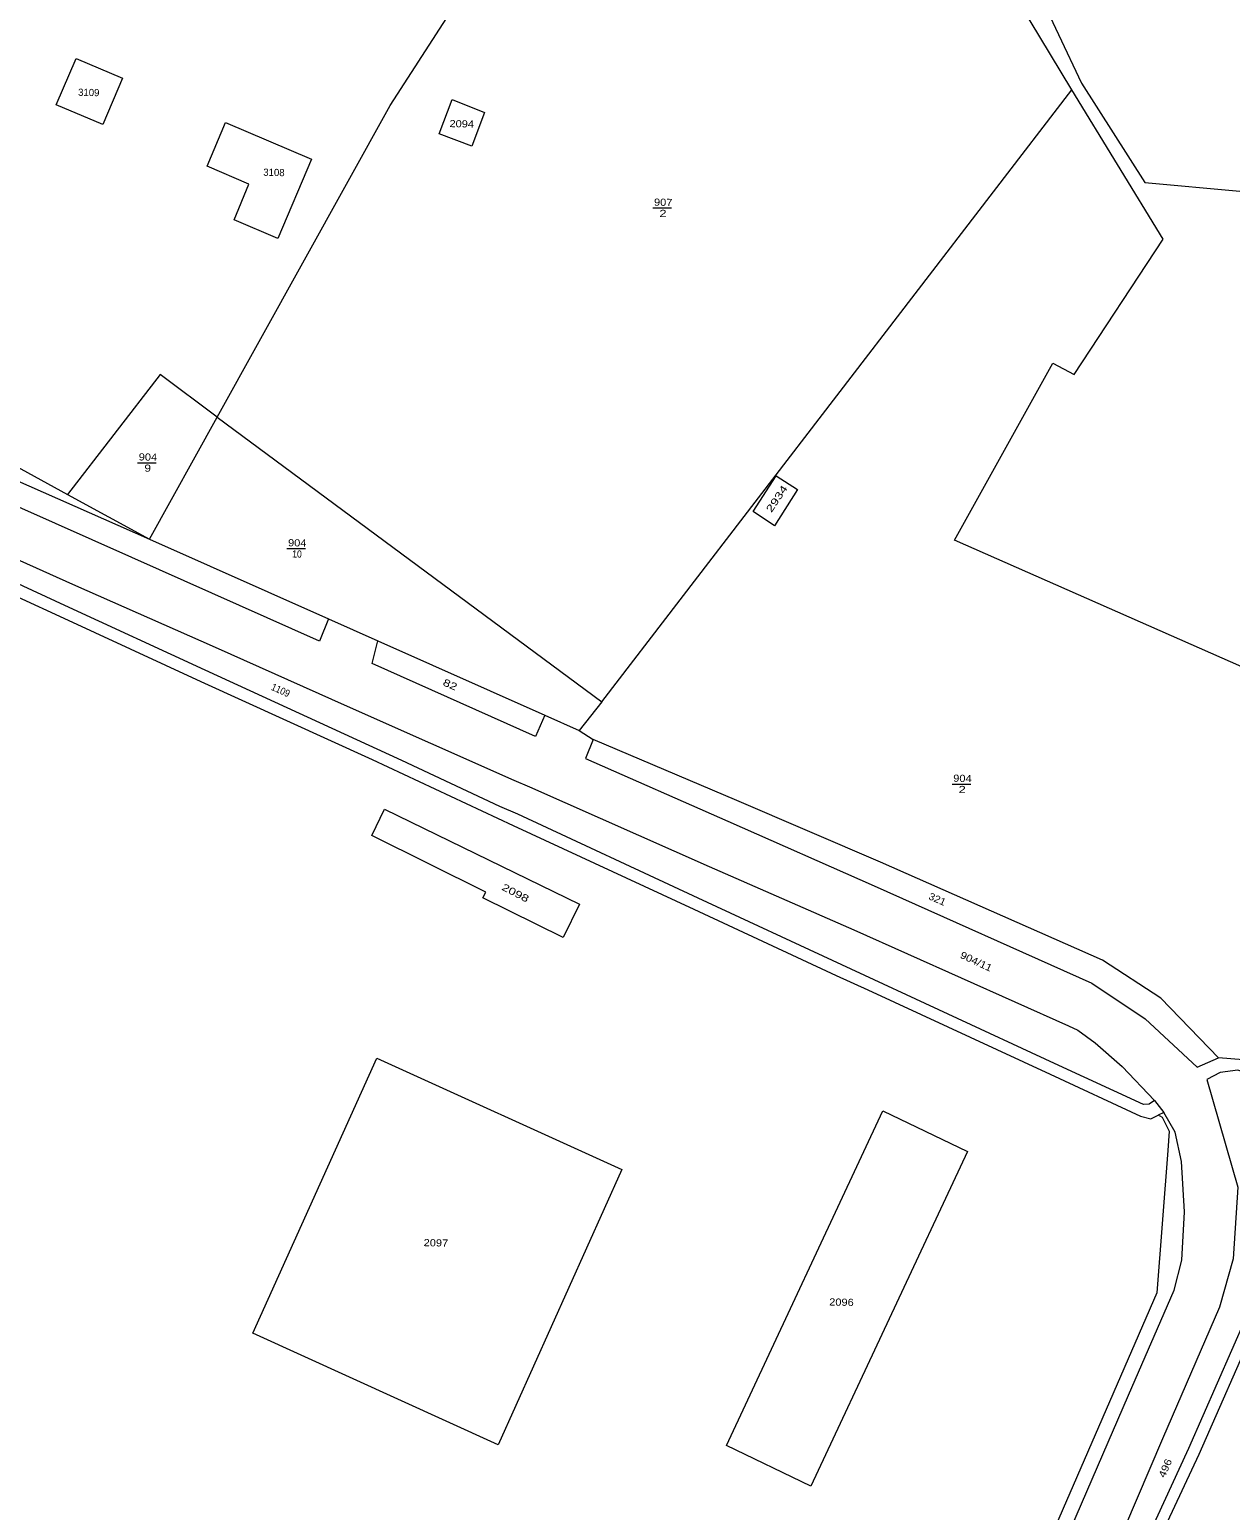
# Model space of a CAD drawing. Extents: x -843400 to -842830, y -1002860 to -1002082.
# Drawn here: x -843097.6 to -842930.2, y -1002726.5 to -1002520 of the extents above; entities that cross this region are included whole.
import ezdxf
from ezdxf.enums import TextEntityAlignment as Align

# ---------------------------------------------------------------- set-up
doc = ezdxf.new("R2010")
doc.units = 0
doc.header["$LTSCALE"] = 0.4
for name, color, linetype, lineweight in [('32', 7, 'Continuous', 13), ('34', 7, 'Continuous', 13), ('35', 7, 'Continuous', 13), ('38', 7, 'Continuous', 13), ('40', 7, 'Continuous', 13), ('43', 7, 'Continuous', 13)]:
    doc.layers.add(name, color=color, linetype=linetype, lineweight=lineweight)

msp = doc.modelspace()

# ---------------------------------------------------------------- linework, layer by layer
at = {"layer": '32'}
for p, q in [((-843017.83, -1002613.7), (-842952.33, -1002528.36)), ((-843055.92, -1002602.16), (-843049.06, -1002605.21)), ((-842940.79, -1002669.32), (-842939.49, -1002671))]:
    msp.add_line(p, q, dxfattribs=at)
for points in [[(-842917.26, -1002663.21), (-842904.25, -1002619.58), (-842968.69, -1002591.19), (-842954.99, -1002566.47), (-842952.01, -1002568.05), (-842939.57, -1002549.22), (-842952.33, -1002528.36), (-842968.38, -1002501.67), (-842999.65, -1002478.78), (-842992.16, -1002464.73), (-842985.04, -1002466.11)], [(-843071.44, -1002574), (-843047.33, -1002530.57), (-843031.55, -1002506.04), (-843010.14, -1002473.05)], [(-843211.56, -1002530.68), (-843208.79, -1002526.68), (-843203.39, -1002526.24), (-843127.17, -1002565.66), (-843092.3, -1002584.79), (-843080.9, -1002591.04)], [(-843215.33, -1002546.59), (-843193.12, -1002556.57), (-843172, -1002566.13), (-843153.26, -1002574.59), (-843132, -1002584.19), (-843109.23, -1002594.52), (-843093.46, -1002601.76), (-843073.75, -1002610.86), (-843049.84, -1002621.77), (-843030.19, -1002630.96), (-843005, -1002642.63), (-842985.15, -1002651.86), (-842980.77, -1002653.89), (-842955.35, -1002665.65), (-842942.73, -1002671.51), (-842941.29, -1002671.85), (-842940.287, -1002671.376)], [(-843080.9, -1002591.04), (-843071.44, -1002574), (-843079.42, -1002568.09), (-843092.3, -1002584.79)], [(-843071.44, -1002574), (-843017.83, -1002613.7), (-843021, -1002617.7)], [(-843025.79, -1002615.57), (-843021, -1002617.7), (-843019.03, -1002618.97)], [(-842949.73, -1002770.53), (-842948.12, -1002770.28), (-842947.09, -1002769.45), (-842946.99, -1002769.3), (-842946.43, -1002768.26), (-842946.36, -1002766.94), (-842947.25, -1002754.97), (-842947.02, -1002748.98), (-842946.95, -1002748.51), (-842945.3, -1002742.1), (-842942.37, -1002735.33), (-842934.56, -1002718.61), (-842926.46, -1002700.13), (-842920.81, -1002683.35), (-842919.88, -1002680.59), (-842915.57, -1002667.81), (-842928.42, -1002663.65), (-842931.89, -1002663.34)]]:
    msp.add_lwpolyline(points, dxfattribs=at)
at = {"layer": '34'}
for p, q in [((-843010.721, -1002544.851), (-843008.125, -1002544.851)), ((-843082.549, -1002580.375), (-843079.953, -1002580.375)), ((-843061.735, -1002592.345), (-843059.139, -1002592.345)), ((-842969.007, -1002625.185), (-842966.411, -1002625.185))]:
    msp.add_line(p, q, dxfattribs=at)
at = {"layer": '38'}
for points in [[(-843091.11, -1002524), (-843084.65, -1002526.76), (-843087.4, -1002533.21), (-843093.89, -1002530.47)], [(-843038.68, -1002529.71), (-843034.21, -1002531.52), (-843035.98, -1002536.21), (-843040.53, -1002534.5)], [(-843070.28, -1002532.94), (-843058.33, -1002538.06), (-843063.01, -1002549.11), (-843069.09, -1002546.48), (-843067.04, -1002541.51), (-843072.85, -1002539)], [(-842996.74, -1002587.18), (-842993.55, -1002582.19), (-842990.54, -1002584.1), (-842993.76, -1002589.17)], [(-843048.13, -1002628.68), (-843020.96, -1002641.94), (-843023.23, -1002646.57), (-843034.42, -1002641.06), (-843034, -1002640.24), (-843049.91, -1002632.37)], [(-843015.03, -1002678.95), (-843032.3, -1002717.35), (-843066.48, -1002701.76), (-843049.21, -1002663.43)], [(-843000.45, -1002717.4), (-842978.65, -1002670.77), (-842966.88, -1002676.43), (-842988.69, -1002723.07)]]:
    msp.add_lwpolyline(points, close=True, dxfattribs=at)
at = {"layer": '40'}
msp.add_lwpolyline([(-843160.48, -1002346.53), (-843130.91, -1002349.42), (-843135.89, -1002376.13), (-843137.14, -1002382.83), (-843106.81, -1002397.6), (-843074.76, -1002421.55), (-843056.97, -1002434.86), (-843014.68, -1002358.16), (-842987.77, -1002367.07), (-842967.67, -1002372.97), (-842947.11, -1002381.03), (-842989.7, -1002460.5), (-842985.04, -1002466.11), (-842976.06, -1002481.3), (-842960.58, -1002507.03), (-842950.97, -1002527.42), (-842942.15, -1002541.29), (-842902.4, -1002544.91), (-842896.82, -1002551.16), (-842896.49, -1002560.21), (-842897.95, -1002605.27), (-842896.46, -1002622.59)], dxfattribs=at)
at = {"layer": '43'}
for points in [[(-843205.3, -1002533.74), (-843157.95, -1002556.9), (-843154.65, -1002558.44), (-843080.9, -1002591.04), (-843055.92, -1002602.16), (-843057.2, -1002605.27), (-843083.34, -1002593.57), (-843099.52, -1002586.37), (-843121.47, -1002576.61), (-843143.39, -1002566.85), (-843160.74, -1002559.11), (-843172.97, -1002553.37), (-843185.06, -1002547.3), (-843201.23, -1002539.36), (-843206.78, -1002537.03), (-843207.67, -1002536.02), (-843206.85, -1002534.51)], [(-843049.06, -1002605.21), (-843025.79, -1002615.57), (-843027.1, -1002618.54), (-843049.87, -1002608.38)], [(-842931.89, -1002663.34), (-842939.92, -1002655.02), (-842948.06, -1002649.75), (-842979, -1002636.06), (-842999, -1002627.47), (-843019.03, -1002618.97), (-843020.11, -1002621.63), (-843000.28, -1002630.34), (-842979.87, -1002639.39), (-842949.52, -1002652.93), (-842942.08, -1002657.9), (-842934.85, -1002664.66)], [(-842948.56, -1002768.3), (-842947.94, -1002767.12), (-842948.92, -1002755.12), (-842948.68, -1002748.71), (-842946.84, -1002741.5), (-842943.78, -1002734.66), (-842936.02, -1002717.81), (-842928, -1002699.57), (-842922.39, -1002682.86), (-842917.91, -1002669.43), (-842917.91, -1002668.95), (-842918.75, -1002668.47), (-842929.16, -1002665.07), (-842931.62, -1002665.4), (-842933.52, -1002666.36), (-842929.19, -1002681.38), (-842929.83, -1002691.39), (-842931.73, -1002698.15), (-842939.66, -1002716.51), (-842946.75, -1002733.04), (-842949.38, -1002740.61), (-842950.88, -1002748.67), (-842951.06, -1002754.94), (-842949.88, -1002768.58)]]:
    msp.add_lwpolyline(points, close=True, dxfattribs=at)
for points in [[(-843107.3, -1002590.3), (-843091.62, -1002597.29), (-843071.73, -1002606.11), (-843053.35, -1002614.32), (-843030.09, -1002624.64), (-843027.94, -1002625.58), (-843002.86, -1002636.68), (-842982.73, -1002645.53), (-842952.78, -1002658.91), (-842951.5, -1002659.52), (-842949.06, -1002661.26), (-842945.32, -1002664.56), (-842940.79, -1002669.32), (-842941.52, -1002669.83), (-842942.35, -1002669.85), (-842954.74, -1002664.14), (-842984.39, -1002650.37), (-843004.39, -1002641.11), (-843029.55, -1002629.38), (-843032.04, -1002628.29), (-843045.71, -1002621.91), (-843073.14, -1002609.3), (-843092.68, -1002600.28), (-843108.27, -1002593.1)], [(-842953.8, -1002732.13), (-842944.4, -1002710.39), (-842938.04, -1002695.77), (-842936.98, -1002691.57), (-842936.62, -1002684.83), (-842937.04, -1002677.84), (-842937.92, -1002673.74), (-842939.49, -1002671), (-842940.287, -1002671.376), (-842940.07, -1002671.47), (-842939.71, -1002671.63), (-842938.74, -1002673.59), (-842938.95, -1002676.3), (-842940.49, -1002696.12), (-842968.25, -1002760.14)]]:
    msp.add_lwpolyline(points, dxfattribs=at)

# ---------------------------------------------------------------- texts
at = {"layer": '34'}
for s, rotation, width, p in [('907', 358.734, 1.15, (-843009.2925, -1002544.5541)), ('2', 358.734, 1.35, (-843009.327, -1002546.1033)), ('904', 358.734, 1.15, (-843081.119, -1002580.0776)), ('9', 358.734, 1.25, (-843081.1535, -1002581.6274)), ('904', 358.734, 1.15, (-843060.306, -1002592.0476)), ('10', 358.734, 0.9, (-843060.341, -1002593.5972)), ('904', 358.734, 1.15, (-842967.5785, -1002624.8876)), ('2', 358.734, 1.35, (-842967.612, -1002626.4373)), ('904/11', 334.887, 1.15, (-842965.8572, -1002650.3703))]:
    msp.add_text(s, height=1, rotation=rotation, dxfattribs=dict(at, width=width)).set_placement(p, align=Align.CENTER)
at = {"layer": '35'}
for s, p in [('3109', (-843089.3685, -1002529.2372)), ('3108', (-843063.554, -1002540.3845))]:
    msp.add_text(s, height=1, rotation=358.734, dxfattribs=at).set_placement(p, align=Align.CENTER)
for s, rotation, width, p in [('2094', 358.734, 1.15, (-843037.374, -1002533.6076)), ('2934', 56.144, 1.4, (-842993.0354, -1002585.6721)), ('2098', 332.72, 1.35, (-843030.1047, -1002640.8061)), ('2097', 358.734, 1.15, (-843040.9765, -1002689.658)), ('2096', 358.734, 1.15, (-842984.442, -1002697.9316))]:
    msp.add_text(s, height=1, rotation=rotation, dxfattribs=dict(at, width=width)).set_placement(p, align=Align.CENTER)
at = {"layer": '43'}
for s, rotation, width, p in [('82', 336.001, 1.35, (-843040.099, -1002611.362)), ('1109', 335.931, 0.9, (-843064.033, -1002612.009)), ('321', 336.132, 1.1, (-842972.392, -1002641.197)), ('496', 66.785, 1.2, (-842939.375, -1002722.009))]:
    msp.add_text(s, height=1, rotation=rotation, dxfattribs=dict(at, width=width)).set_placement(p)

doc.saveas('drawing.dxf')
